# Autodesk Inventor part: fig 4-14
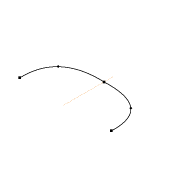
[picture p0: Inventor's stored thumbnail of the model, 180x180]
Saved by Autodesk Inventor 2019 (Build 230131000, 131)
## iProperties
Created: 2012-07
Part Number: fig 4-14
Material: Generic
Document SubType Name: Modeling
Designer: CADCIM
Density: 1 g/cm^3
Appearance: Default
Author: CADCIM
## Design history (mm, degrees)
sketch "Sketch1"
  geometry: L1 (-0.121, 16.232)-(-0.121, 0.498); 5 further points
  constraints: 2 end point, 2 symmetric about line, 1 vertical, 7 other
